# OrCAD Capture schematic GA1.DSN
size A
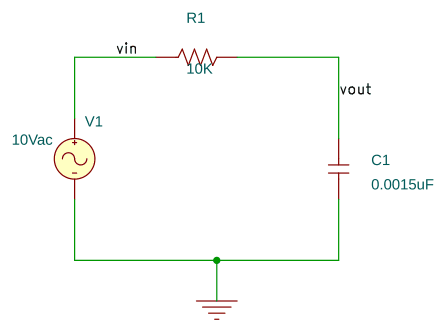
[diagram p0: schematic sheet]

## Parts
C1  0.0015uF  [RAD/CK05]
R1  10K  [AX/RC05]
V1  VAC

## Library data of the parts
C1 = C
R1 = R
V1 = VAC: ACMAG: 10Vac

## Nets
vin: R1.1 V1.1(+)
0: C1.1 V1.2(-)
vout: C1.2 R1.2
